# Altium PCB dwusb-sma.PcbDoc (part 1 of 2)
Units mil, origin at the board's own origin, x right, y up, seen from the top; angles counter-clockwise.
Board outline 1415 x 748.03 mil, 4 copper layers (Component Side, Ground Plane, Power Plane, Solder Side), stack 62.214 mil thick; 104 components, 67 nets, 356 pads, 248 vias.
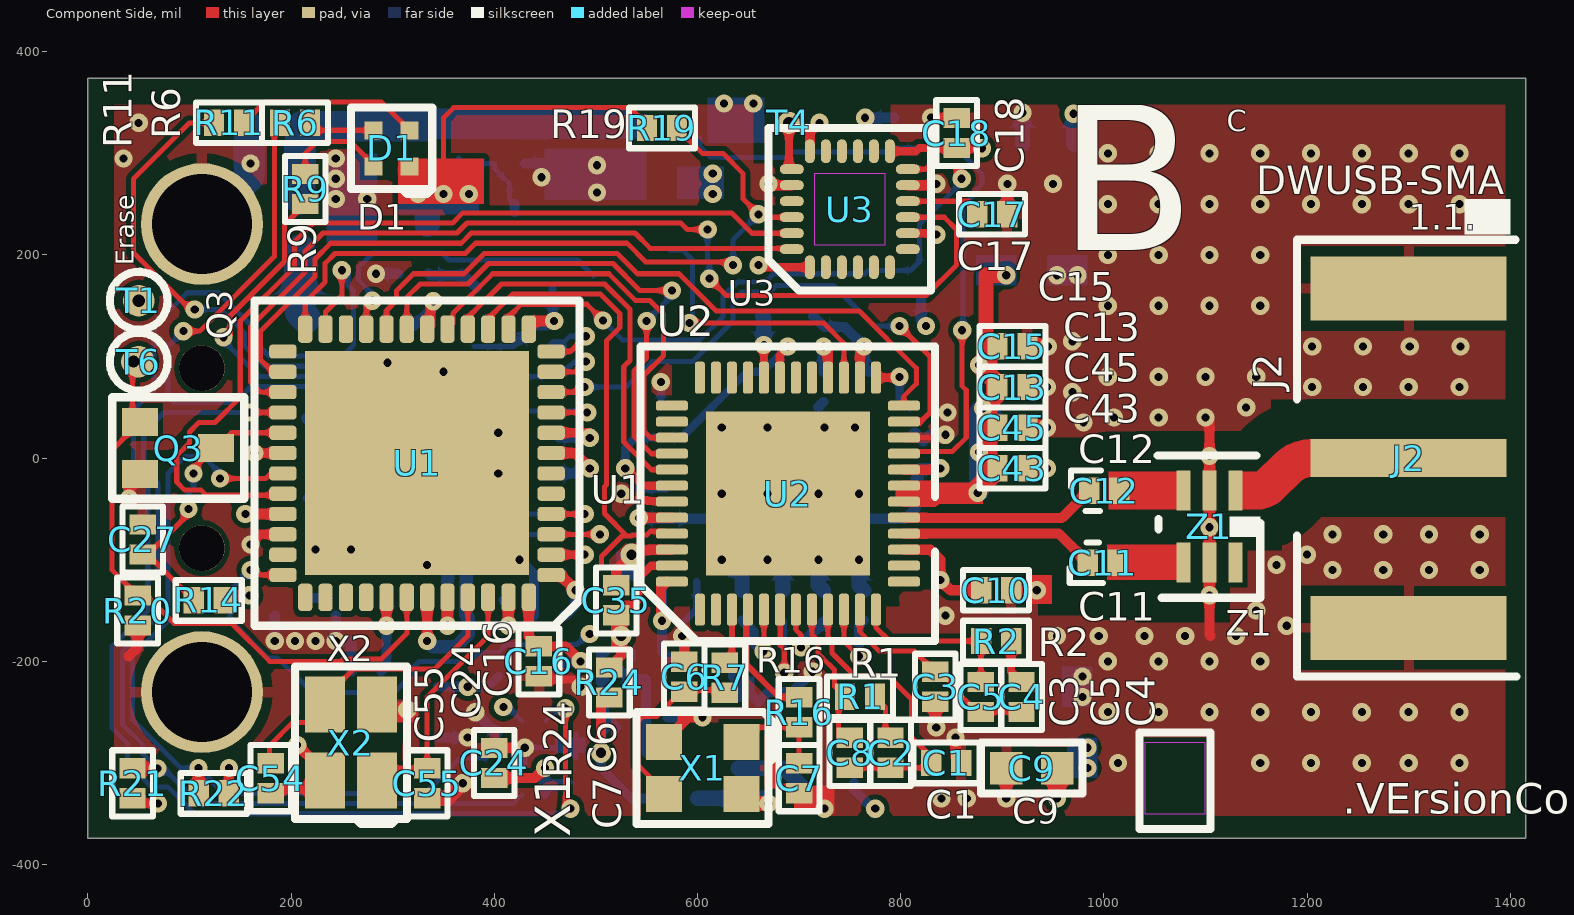
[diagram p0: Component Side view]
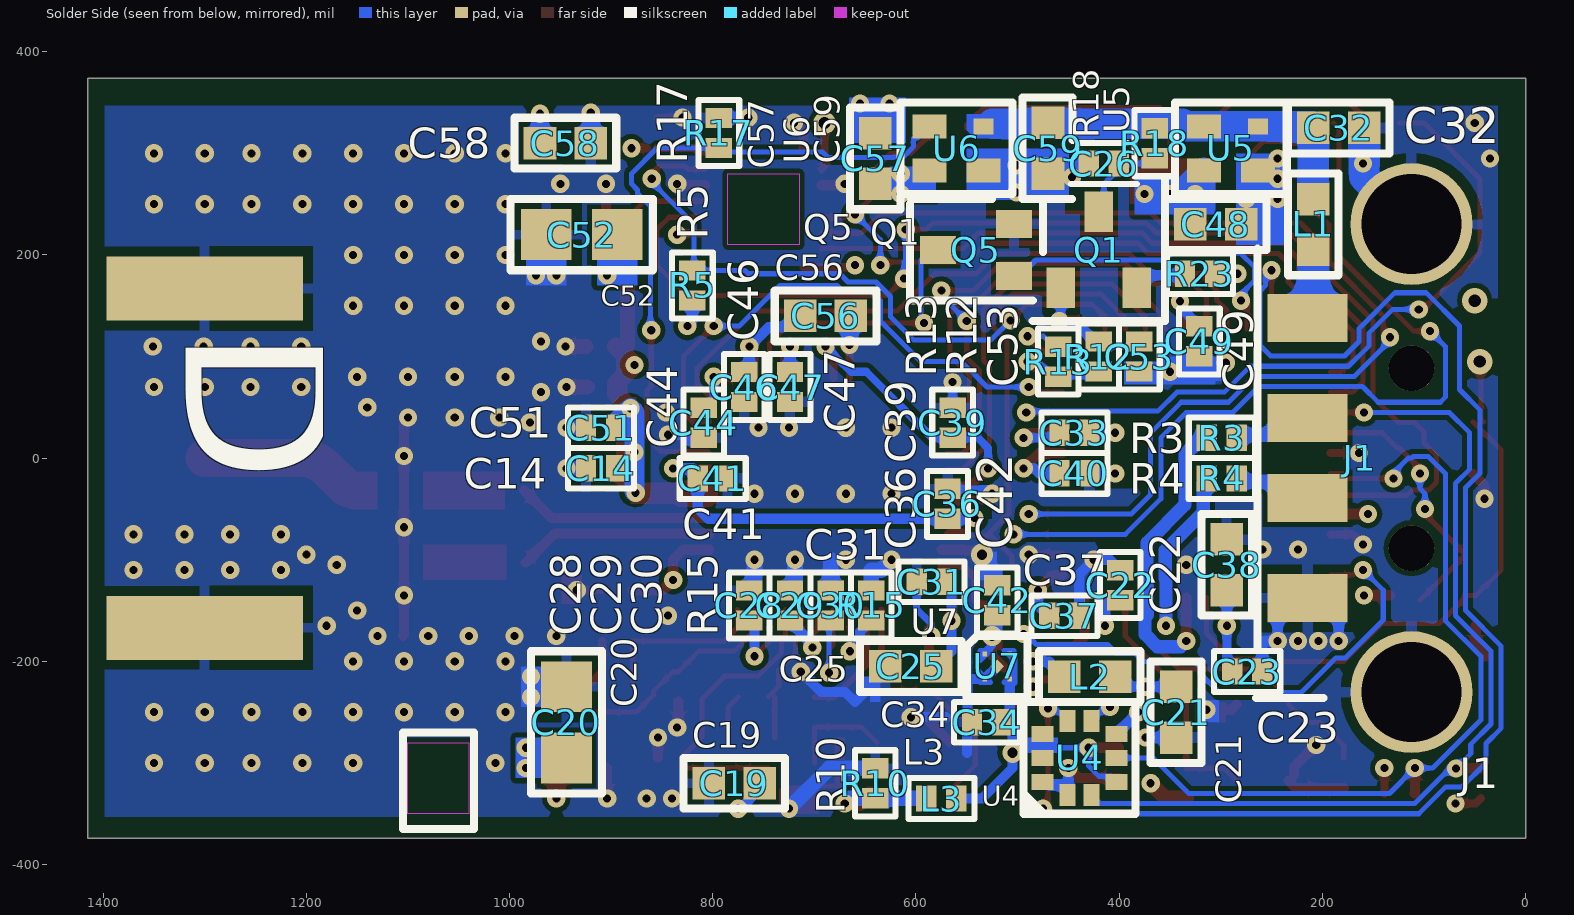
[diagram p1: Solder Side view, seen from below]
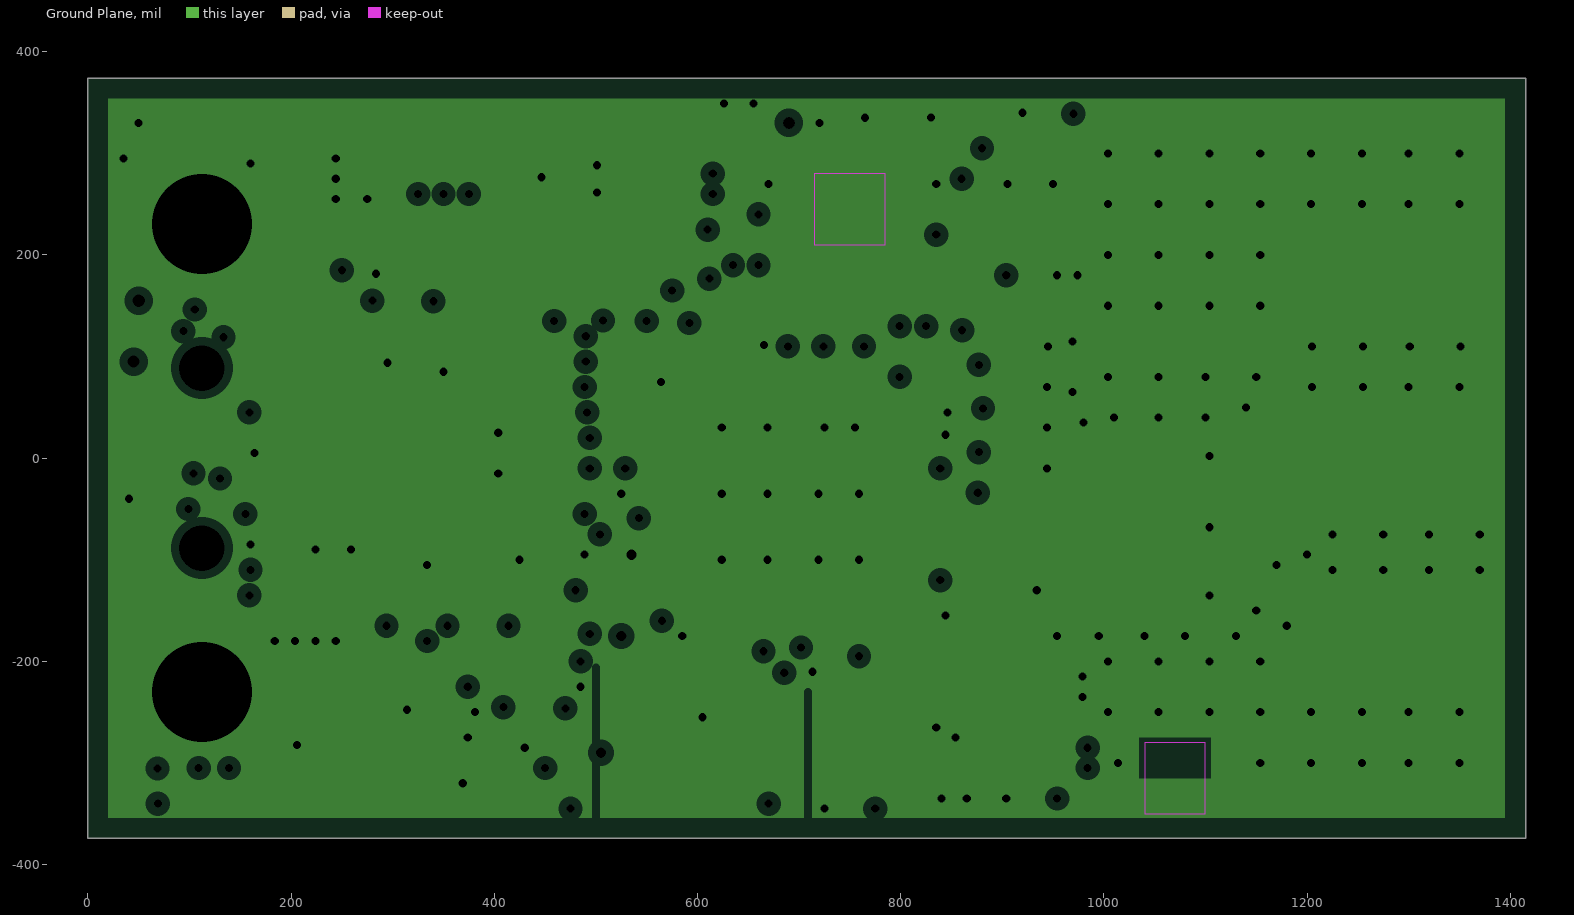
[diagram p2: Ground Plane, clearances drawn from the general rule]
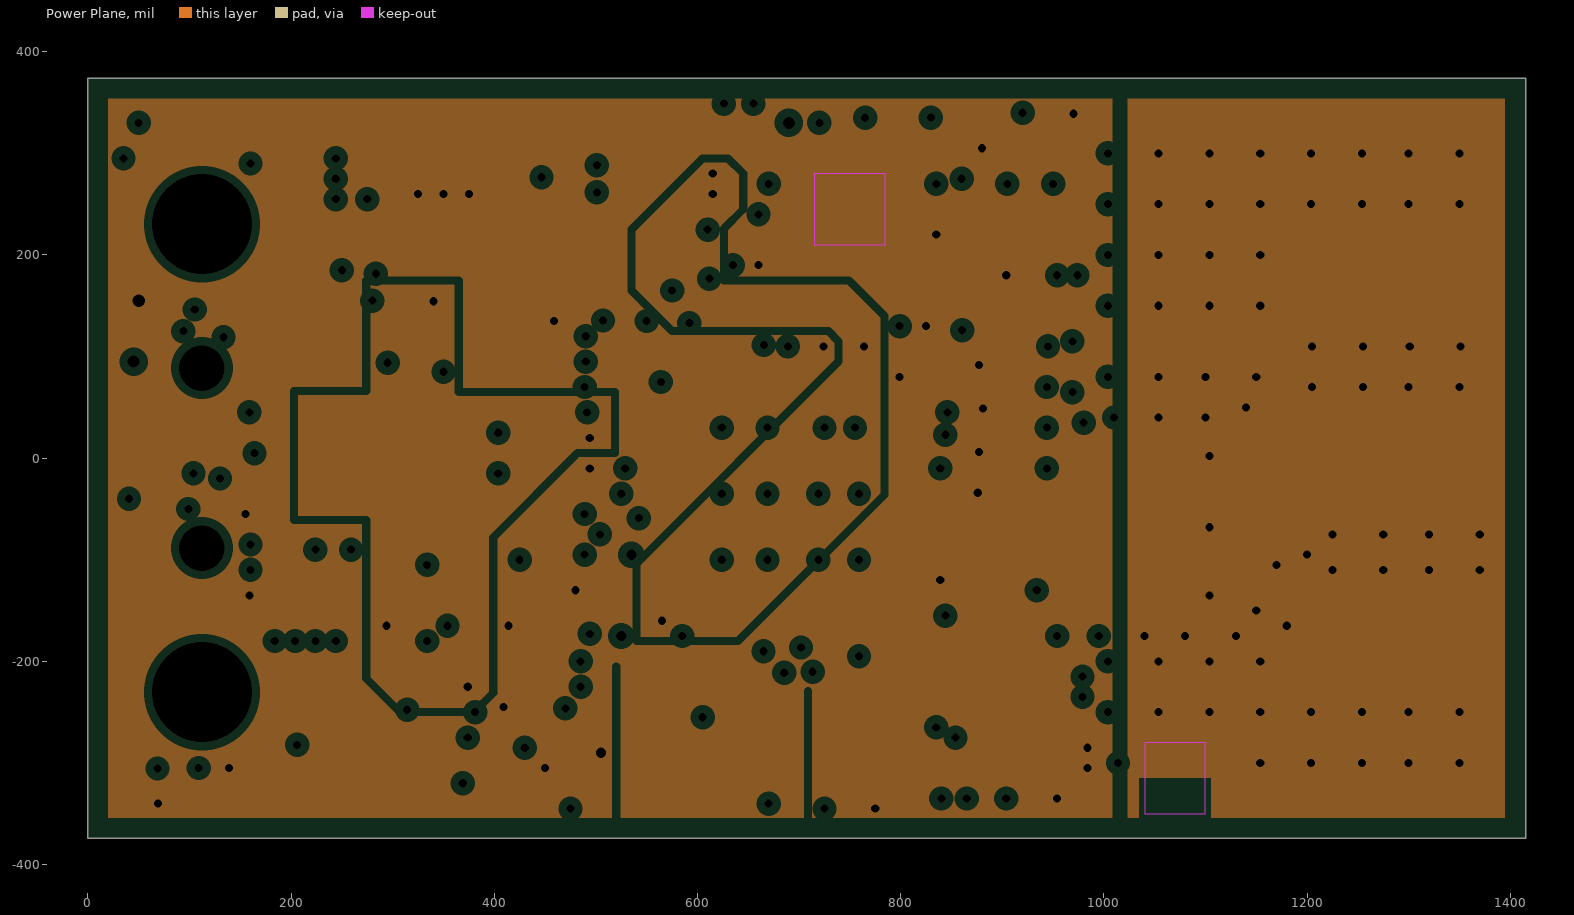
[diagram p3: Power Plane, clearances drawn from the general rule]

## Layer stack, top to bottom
Top Solder: solder mask 0.4, Solder Resist, Dk 3.5
Component Side: signal copper 1.4
Dielectric1: core 20.0787, FR-4, Dk 4.5
Ground Plane: plane copper 1.4, net GND
Dielectric2: prepreg 16.4567, FR-4, Dk 4.5
Power Plane: plane copper 1.4, net (Multiple Nets)
Dielectric3: core 20.0787, FR-4, Dk 4.5
Solder Side: signal copper 1.4
Bottom Solder: solder mask 0.4, Solder Resist, Dk 3.5

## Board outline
0,-374.02 1415,-374.02 1415,374.02 0,374.02

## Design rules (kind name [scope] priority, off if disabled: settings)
AcuteAngle [All] p1: minimum=7.50000000000000E+0001 checktracksonly=FALSE
AssemblyTestPointUsage [All] p1 off:
AssemblyTestpoint [All] p1 off: testpointundercomponent=TRUE minsize=30 maxsize=100 preferedsize=60 minholesize=0 maxholesize=40 preferedholesize=32 testpointgrid=1 usegrid=TRUE gridtolerance=0.01 allowsidetop=TRUE allowsidebottom=TRUE
Clearance Clearance_1 [(InNamedPolygon('top-ground')) vs InNet('ANTENNA')or InNet('BAL_P')or InNet('BAL_N')or InNet('RF_N')or InNet('RF_P')] p1: gap=39.37
Clearance [All] p2: gap=5
ComponentClearance ComponentClearance_2 [All] p1: gap=10 collisioncheckmode=3 verticalgap=10 showdistances=FALSE
ComponentClearance ComponentClearance_1 [InComponent('T2')] p2: gap=-500 collisioncheckmode=3 verticalgap=-500 showdistances=FALSE
ComponentClearance [InComponent('J1') vs InComponent('J2')] p3: gap=-1000 collisioncheckmode=3 verticalgap=-10000 showdistances=FALSE
DiffPairsRouting [All] p1: maxlimit=10 minlimit=5 mostfreqgap=5 toplayer_minwidth=9.06 toplayer_maxwidth=45 toplayer_prefwidth=9.25 bottomlayer_minwidth=9.06 bottomlayer_maxwidth=45 bottomlayer_prefwidth=9.25 maxuncoupledlength=500
FabricationTestPointUsage [All] p1 off: valid=0 allowmultiple=FALSE
FabricationTestpoint [All] p1 off: side=3 testpointundercomponent=TRUE minsize=30 maxsize=100 preferedsize=60 minholesize=0 maxholesize=40 preferedholesize=32 testpointgrid=1 allowsidetop=TRUE allowsidebottom=TRUE usegrid=TRUE gridtolerance=0.01
Height [All] p1: minheight=0 maxheight=2000 prefheight=500
HoleSize [All] p1: absolutevalues=TRUE maxlimit=300 minlimit=5 maxpercent=80.000 minpercent=20.000
MinimumAnnularRing [All] p1: minimumring=5
MinimumSolderMaskSliver [All] p1: minsoldermaskwidth=4
PlaneClearance [All] p1: clearance=8
PlaneConnect [All] p1: planeconnectstyle=Direct reliefexpansion=20 reliefentries=4 reliefconductorwidth=10 reliefairgap=10
PolygonConnect PolygonConnect_1 [(InPadClass('All Pads'))] p1: connectstyle=Relief reliefconductorwidth=10 reliefentries=4 polygonreliefangle="90 Angle" airgapwidth=10
PolygonConnect [All] p2: connectstyle=Direct reliefconductorwidth=10 reliefentries=4 polygonreliefangle="90 Angle" airgapwidth=10
RoutingVias [All] p1: holewidth=12 width=24 viastyle="Through Hole" minholewidth=6 minwidth=16 maxholewidth=40 maxwidth=50
SilkToSilkClearance [All] p1: silktosilkclearance=0
SilkToSolderMaskClearance SilkscreenOverComponentPads [IsPad] p1: minsilkscreentomaskgap=0 clearancetoexposedcopper=TRUE
SolderMaskExpansion [All] p1: expansion=0
Width "Schematic Width Constraint_4" [InNet('BAL_N')] p1: maxlimit=14.3 minlimit=13.43 preferedwidth=13.66 impedancedriven=TRUE minimp=80.000000 maximp=82.000000 favimp=81.450000
Width "Schematic Width Constraint_3" [InNet('RF_P')] p2: maxlimit=14.3 minlimit=13.43 preferedwidth=13.66 impedancedriven=TRUE minimp=80.000000 maximp=82.000000 favimp=81.450000
Width "Schematic Width Constraint_2" [InNet('RF_N')] p3: maxlimit=14.3 minlimit=13.43 preferedwidth=13.66 impedancedriven=TRUE minimp=80.000000 maximp=82.000000 favimp=81.450000
Width "Schematic Width Constraint_1" [InNet('BAL_P')] p4: maxlimit=14.3 minlimit=13.43 preferedwidth=13.66 impedancedriven=TRUE minimp=80.000000 maximp=82.000000 favimp=81.450000
Width [All] p5: maxlimit=200 minlimit=5 preferedwidth=5
17 further rules are at their usual default settings.

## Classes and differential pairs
component class sam4s-mpu9250: C9 C16 C17 C18 C19 C21 C22 C23 C24 C26 C27 C32 C33 C37 C38 C40 C48 C49 C53 C54 C55 C58 D1 J1 L1 L2 Q1 Q3 R3 R4 R5 R6 R9 R11 R12 R13 R14 R18 R19 R20 R21 R22 R23 T1 T4 T6 U1 U3 U4 U5 X2
component class dw1000: C1 C2 C3 C4 C5 C6 C7 C8 C10 C11 C12 C13 C14 C15 C20 C25 C28 C29 C30 C31 C34 C35 C36 C39 C41 C42 C43 C44 C45 C46 C47 C51 C52 C56 C57 C59 J2 L3 Q5 R1 R2 R7 R10 R15 R16 R17 R24 U2 U6 U7 X1 Z1
component class dwusb-sma: A1
differential pair RF: +RF_P -RF_N
differential pair USB-DATA: +USB-DATA_P -USB-DATA_N
differential pair BAL: +BAL_P -BAL_N
differential pair USB: +USB_P -USB_N

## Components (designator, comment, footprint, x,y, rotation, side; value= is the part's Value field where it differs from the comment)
A1 "A_DG-OUTLINE-DG-270X100" DG-270X100 1435,-550 r180 top
C1 "C_CAP_0402" 0402 845,-300 r180 top
C2 "C_CAP_0402" 0402 790,-290 r90 top
C3 "C_CAP_0402" 0402 833.94,-225 r270 top
C4 "C_CAP_0402" 0402 918.94,-235 r90 top
C5 "C_CAP_0402" 0402 878.94,-235 r90 top
C6 "C_CAP_0402" 0402 587,-215 r270 top
C7 "C_CAP_0402" 0402 700,-315 r90 top
C8 "C_CAP_0402" 0402 750,-290 r270 top
C9 "C_CAP_0603" 0603 928.94,-305 r180 top
C10 "C_CAP_0402" 0402 893.94,-130 r0 top
C11 "C_CAP_0402" 0402 998.94,-102.87 r0 top
C12 "C_CAP_0402" 0402 1000.24,-32.01 r0 top
C13 "C_CAP_0402" 0402 910,70 r0 top
C14 "C_CAP_0402" 0402 910,-10 r0 bottom
C15 "C_CAP_0402" 0402 910,110 r0 top
C16 "C_CAP_0402" 0402 443.94,-200 r270 top
C17 "C_CAP_0402" 0402 890,240 r0 top
C18 "C_CAP_0402" 0402 855,320 r90 top
C19 "C_CAP_0603" 0603 778.94,-320 r0 bottom
C20 "C_CAP_0805" 0805 943.94,-260 r90 bottom
C21 "C_CAP_0603" 0603 343.94,-250 r270 bottom
C22 "C_CAP_0402" 0402 398.94,-125 r90 bottom
C23 "C_CAP_0402" 0402 273.94,-210 r180 bottom
C24 "C_CAP_0402" 0402 400,-300 r90 top
C25 "C_CAP_0603" 0603 605,-205 r0 bottom
C26 "C_CAP_0402" 0402 415,290 r0 bottom
C27 "C_CAP_0402" 0402 53.94,-80 r90 top
C28 "C_CAP_0402" 0402 763.94,-145 r90 bottom
C29 "C_CAP_0402" 0402 723.94,-145 r90 bottom
C30 "C_CAP_0402" 0402 683.94,-145 r90 bottom
C31 "C_CAP_0402" 0402 584.53,-121.61 r0 bottom
C32 "C_CAP_0603" 0603 183.94,325 r180 bottom
C33 "C_CAP_0402" 0402 443.94,25 r180 bottom
C34 "C_CAP_0402" 0402 530,-260 r0 bottom
C35 "C_CAP_0402" 0402 520,-140 r90 top
C36 "C_CAP_0402" 0402 568.94,-45 r90 bottom
C37 "C_CAP_0402" 0402 453.94,-155 r180 bottom
C38 "C_CAP_0603" 0603 293.94,-105 r90 bottom
C39 "C_CAP_0402" 0402 563.94,35 r90 bottom
C40 "C_CAP_0402" 0402 443.94,-15 r180 bottom
C41 "C_CAP_0402" 0402 800,-20 r180 bottom
C42 "C_CAP_0402" 0402 520,-140 r90 bottom
C43 "C_CAP_0402" 0402 910,-10 r0 top
C44 "C_CAP_0402" 0402 808.94,35 r270 bottom
C45 "C_CAP_0402" 0402 910,30 r0 top
C46 "C_CAP_0402" 0402 768.94,70 r270 bottom
C47 "C_CAP_0402" 0402 723.94,70 r270 bottom
C48 "C_CAP_0603" 0603 305,230 r180 bottom
C49 "C_CAP_0402" 0402 321,115 r270 bottom
C51 "C_CAP_0402" 0402 910,30 r0 bottom
C52 "C_CAP_0805" 0805 928.94,220 r0 bottom
C53 "C_CAP_0402" 0402 380,100 r270 bottom
C54 "C_CAP_0402" 0402 180,-315 r270 top
C55 "C_CAP_0402" 0402 333.94,-320 r270 top
C56 "C_CAP_0603" 0603 688.94,140 r180 bottom
C57 "C_CAP_0603" 0603 640,295 r90 bottom
C58 "C_CAP_0603" 0603 945,310 r180 bottom
C59 "C_CAP_0603" 0603 470,305 r270 bottom
D1 "LED RGB SQUARE CLEAR SMD" 0404-3C-LED 298.94,305 r180 top
J1 "J_USBA-PLUG_48037-2200" 48037-2200 3.94,0 r90 bottom locked
J2 "J01340" 142-0701-801 1415,0 r270 top locked
L1 "L_IND_0603" 0603 208.94,230 r90 bottom
L2 "L_IND_0603" 0603 428.94,-215 r0 bottom
L3 "L_IND_0402" 0402 575,-335 r0 bottom
Q1 "Q_JFET-P_SOT23" SOT23 420,205 r90 bottom
Q3 "Q00171" SC70 88.94,10 r0 top
Q5 "Q00171" SC70 541,205 r0 bottom
R1 "R_RES_0402" 0402 760,-235 r0 top
R2 "R_RES_0402" 0402 893.94,-180 r180 top
R3 "R_RES_0402" 0402 298.94,20 r180 bottom
R4 "R_RES_0402" 0402 298.94,-20 r180 bottom
R5 "R_RES_0402" 0402 820,170 r270 bottom
R6 "R_RES_0402" 0402 203.94,330 r0 top
R7 "R_RES_0402" 0402 627,-216 r270 top
R9 "R_RES_0402" 0402 213.94,265 r90 top
R10 "R_RES_0402" 0402 640,-320 r270 bottom
R11 "R_RES_0402" 0402 138.94,330 r0 top
R12 "R_RES_0402" 0402 420,100 r90 bottom
R13 "R_RES_0402" 0402 460,95 r270 bottom
R14 "R_RES_0402" 0402 118.94,-140 r0 top
R15 "R_RES_0402" 0402 643.94,-145 r270 bottom
R16 "R_RES_0402" 0402 700,-250 r270 top
R17 "R_RES_0402" 0402 793.94,320 r270 bottom
R18 "R_RES_0402" 0402 365,310 r270 bottom
R19 "R_RES_0402" 0402 565,325 r180 top
R20 "R_RES_0402" 0402 48.94,-150 r90 top
R21 "R_RES_0402" 0402 43.94,-320 r270 top
R22 "R_RES_0402" 0402 123.94,-330 r0 top
R23 "R_RES_0402" 0402 320.44,181.5 r0 bottom
R24 "R_RES_0402" 0402 513.31,-220.75 r90 top
T1 "T_TESTPOINT-PAD_T31ES" T31ES 50,155 r270 top
T4 "T_TESTPOINT_H22D12EDS" H22D12EDS 690,330 r0 top locked
T6 "T_TESTPOINT-PAD_T31ES" T31ES 50,95 r270 top
U1 "U00965" QFN48 323.94,-5 r180 top
U2 "U00956" QFN48-6M0 688.94,-35 r90 top
U3 "U00945" MPU-9250 750,245 r90 top
U4 "U01153" LGA10-2M5 438.94,-295 r90 bottom
U5 "U_LXDC2HL_LXDC2HL" LXDC2HL 290,305 r0 bottom
U6 "U00987" LXDC2HL 560,305 r0 bottom
U7 "U_TCR2LN_SDFN4" SDFN4 520,-205 r180 bottom
X1 "X_XTAL4P2G_ECX-2236" 7Z-2M0X1M6-4P 605,-305 r180 top
X2 "X_XTAL4P2G_ECX-2236" ECX-2236 258.94,-280 r90 top
Z1 "Z_WE-BAL_0805-6" 0805-6 1103.94,-67.44 r270 top

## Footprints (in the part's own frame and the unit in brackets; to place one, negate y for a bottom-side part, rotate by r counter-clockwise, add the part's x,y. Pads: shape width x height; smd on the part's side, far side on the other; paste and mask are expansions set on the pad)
7Z-2M0X1M6-4P [mm]
  rect 0.9x0.9 smd: 1(-0.97,-0.65) 2(0.97,-0.65) 3(0.97,0.65) 4(-0.97,0.65)
  silkscreen extent -1.78,-1.4 1.65,1.4, body extent -1.28,-1.05 1.25,1.05, height 0.75
142-0701-801 [mil]
  rect 37.4x193 smd paste-1000: 1(0,-115)
  rect 63x193 smd paste-1000: 2(-167,-115) 3(167,-115)
  rect 63x193 smd far side paste-1000: 4(167,-115) 5(-167,-115)
  silkscreen extent -215,-225 215,-9, body extent -187,-187 188,375, height 171
0402 [mil]
  rect 20x26 smd: 1(-14.76,0) 2(14.76,0)
  silkscreen extent -32,-20 32,20, body extent -20,-10 20,10, height 14
0404-3C-LED [mm]
  rect 0.45x0.45 smd: 1(-0.45,0.45) 2(0.45,0.45) 3(0.45,-0.45) 4(-0.45,-0.45)
  silkscreen extent -1.02,-1.02 1.02,1.14, body extent -0.5,-0.5 0.5,0.5, height 0.25
0603 [mil]
  rect 32x32 smd: 1(-25,0) 2(25,0)
  silkscreen extent -50,-25 50,25, body extent -30,-15 30,15, height 30
0805 [mil]
  rect 50x50 smd: 1(-35,0) 2(35,0)
  silkscreen extent -70,-35 70,35, body extent -40,-25 40,25, height 50
0805-6 [mm]
  rect 1x0.35 smd: 1(-0.9,0.65) 2(-0.9,0) 3(-0.9,-0.65) 4(0.9,-0.65) 5(0.9,0) 6(0.9,0.65)
  silkscreen extent -1.78,-1.29 1.78,1.27, body extent -0.67,-1.05 0.67,1.05, height 0.95
48037-2200 [mm]
  rect 1.2x2 smd: 1(3.5,5.35) 2(1,5.35) 3(-1,5.35) 4(-3.5,5.35)
  round 3.048 hole 2.5: 5(5.85,2.75) 6(-5.85,2.75)
  round 1.143 hole 1.143 unplated: ""(-2.25,2.75) ""(2.25,2.75)
  silkscreen extent -6,4.95 5.24,6.63, body extent -6.02,-15.01 6.03,5.94, height 2.1
DG-270X100 [mil]
  Keep-Out Layer region: 394.99,-269.99 394.99,-199.99 334.99,-199.99 334.99,-269.99
ECX-2236 [mm]
  rect 1.4x1 smd: 1(-0.95,-0.65) 2(0.95,-0.65) 3(0.95,0.65) 4(-0.95,0.65)
  silkscreen extent -2.03,-1.4 1.91,1.4, body extent -1.3,-1.05 1.3,1.05, height 0.65
H22D12EDS [mil]
  round 22 hole 12: 1(0,0)
  body extent -11,-11 11,11, height 1
LGA10-2M5 [mm]
  rect 0.55x0.4 smd: 1(-0.925,0.3) 2(-0.925,-0.3) 6(0.925,-0.3) 7(0.925,0.3)
  rect 0.4x0.55 smd: 3(-0.6,-0.925) 4(0,-0.925) 5(0.6,-0.925) 8(0.6,0.925) 9(0,0.925) 10(-0.6,0.925)
  silkscreen extent -1.4,-1.4 1.4,1.4, body extent -1.25,-1.25 1.25,1.25, height 1.1
LXDC2HL [mm]
  rect 0.5x0.4 smd: 1(-0.675,-0.55)
  rect 0.85x0.6 smd: 2(0.675,-0.55) 3(0.675,0.55) 4(-0.675,0.55)
  Component Side region: -1.1,-0.85 -0.25,-0.85 -0.25,-0.45 -0.45,-0.25 -1.1,-0.25
  silkscreen extent -1.4,-1.14 1.4,1.14, body extent -1.25,-1 1.25,1, height 0.6
MPU-9250 [mm]
  rrect100% 0.6x0.25 smd: 1(-1.45,1) 2(-1.45,0.6) 3(-1.45,0.2) 4(-1.45,-0.2) 5(-1.45,-0.6) 6(-1.45,-1) 13(1.45,-1) 14(1.45,-0.6) 15(1.45,-0.2) 16(1.45,0.2) 17(1.45,0.6) 18(1.45,1)
  rrect100% 0.25x0.6 smd: 7(-1,-1.45) 8(-0.6,-1.45) 9(-0.2,-1.45) 10(0.2,-1.45) 11(0.6,-1.45) 12(1,-1.45) 19(1,1.45) 20(0.6,1.45) 21(0.2,1.45) 22(-0.2,1.45) 23(-0.6,1.45) 24(-1,1.45)
  Keep-Out Layer region: -0.889,-0.889 0.889,-0.889 0.889,0.889 -0.889,0.889
  silkscreen extent -2.03,-2.03 2.03,2.03, body extent -1.5,-1.5 1.5,1.5, height 1.1
QFN48 [mil]
  rrect50% 27x14 smd: 1(-132,110) 2(-132,90) 3(-132,70) 4(-132,50) 5(-132,30) 6(-132,10) 7(-132,-10) 8(-132,-30) 9(-132,-50) 10(-132,-70) 11(-132,-90) 12(-132,-110) 25(132,-110) 26(132,-90) 27(132,-70) 28(132,-50) 29(132,-30) 30(132,-10) 31(132,10) 32(132,30) 33(132,50) 34(132,70) 35(132,90) 36(132,110)
  rrect50% 14x27 smd: 13(-110,-132) 14(-90,-132) 15(-70,-132) 16(-50,-132) 17(-30,-132) 18(-10,-132) 19(10,-132) 20(30,-132) 21(50,-132) 22(70,-132) 23(90,-132) 24(110,-132) 37(110,132) 38(90,132) 39(70,132) 40(50,132) 41(30,132) 42(10,132) 43(-10,132) 44(-30,132) 45(-50,132) 46(-70,132) 47(-90,132) 48(-110,132)
  rect 220.47x220.47 smd paste-1000: 49(0,0)
  silkscreen extent -160,-160 160,160, body extent -138,-138 138,138, height 35
QFN48-6M0 [mm]
  rrect50% 0.8x0.25 smd: 1(-2.9,2.2) 2(-2.9,1.8) 3(-2.9,1.4) 4(-2.9,1) 5(-2.9,0.6) 6(-2.9,0.2) 7(-2.9,-0.2) 8(-2.9,-0.6) 9(-2.9,-1) 10(-2.9,-1.4) 11(-2.9,-1.8) 12(-2.9,-2.2) 25(2.9,-2.2) 26(2.9,-1.8) 27(2.9,-1.4) 28(2.9,-1) 29(2.9,-0.6) 30(2.9,-0.2) 31(2.9,0.2) 32(2.9,0.6) 33(2.9,1) 34(2.9,1.4) 35(2.9,1.8) 36(2.9,2.2)
  rrect50% 0.25x0.8 smd: 13(-2.2,-2.9) 14(-1.8,-2.9) 15(-1.4,-2.9) 16(-1,-2.9) 17(-0.6,-2.9) 18(-0.2,-2.9) 19(0.2,-2.9) 20(0.6,-2.9) 21(1,-2.9) 22(1.4,-2.9) 23(1.8,-2.9) 24(2.2,-2.9) 37(2.2,2.9) 38(1.8,2.9) 39(1.4,2.9) 40(1,2.9) 41(0.6,2.9) 42(0.2,2.9) 43(-0.2,2.9) 44(-0.6,2.9) 45(-1,2.9) 46(-1.4,2.9) 47(-1.8,2.9) 48(-2.2,2.9)
  rect 4.1x4.1 smd paste-25.4: 49(0,0)
  silkscreen extent -3.68,-3.68 3.68,3.68, body extent -3,-3 3,3, height 1.19
SC70 [mm]
  rect 0.9x0.7 smd: 1(-0.95,0.65) 2(-0.95,-0.65) 3(0.95,0)
  silkscreen extent -1.65,-1.27 1.65,1.27, body extent -1.2,-1 1.2,1, height 1
SDFN4 [mm]
  rect 0.12x0.12 smd paste+0 mask-0.051: 1(-0.312,0.312) 2(-0.312,-0.312) 3(0.312,-0.312) 4(0.312,0.312)
  rect 0.25x0.25 smd rot 135 paste+0 mask+0.051: 5(0,0)
  Component Side region: -0.425,0.145 -0.425,0.4 -0.17,0.4
  Component Side region: -0.425,-0.4 -0.425,-0.145 -0.17,-0.4
  Component Side region: 0.425,-0.4 0.425,-0.145 0.17,-0.4
  Component Side region: 0.425,0.145 0.425,0.4 0.17,0.4
  Component Side lines w0.127: 0.425,-0.4 0.17,-0.4 0.425,-0.145 0.425,-0.4 ; 0.425,0.145 0.17,0.4 0.425,0.4 0.425,0.145 ; -0.17,-0.4 -0.425,-0.4 -0.425,-0.145 -0.17,-0.4 ; -0.17,0.4 -0.425,0.4 -0.425,0.145 -0.17,0.4
  silkscreen extent -0.76,-0.76 0.76,0.76, body extent -0.4,-0.4 0.4,0.4, height 0.4
SOT23 [mil]
  rect 40x28 smd: 1(-37.4,37.4) 2(-37.4,-37.4) 3(37.4,0)
  silkscreen extent -70,-65 70,65, body extent -55,-57 55,57, height 39
T31ES [mil]
  round 31 smd paste-100: 1(0,0)
  silkscreen extent -28,-28 28,28

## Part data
A1: library part A02065, "Ciholas Blank DWUSB SMA PCB Revision 1.1.0"
C1 C3 C15 C16 C17 C18 C22 C23 C24 C27 C28 C29 C30 C31 C33 C34 C35 C36 C37 C39 C40 C41 C44 C46 C47 C49 C51 C53: library part C00136, "Capacitor 100nF 10V Ceramic X5R 0402"
C2: library part C00457, "Ceramic Capacitor 0402 27pF NP0"
C4: library part C00460, "CAP CER 820pF 50V 2% NP0 0402"
C5: library part C00459, "CAP CER 18PF 50V 2% NP0 0402"
C6 C7 C11 C12: library part C00461, "CAP CER 12pF 50V 2% NP0 0402"
C8 C54 C55: library part C00458, "Ceramic Capacitor 0402 1.2pF NP0"
C9 C19 C21 C25 C56 C58: library part C00213
C10: library part C00137, "Capacitor 10nF 25V Ceramic X7R 0402"
C13 C14: library part C00441, "CAP CER 10PF 50V 5% NP0 0402"
C20 C52: library part C00468, "CAP CER 47UF 6.3V 20% X5R 0805"
C26: library part C00434, "CAP CER 100PF 50V 5% NP0 0402"
C32 C59: library part C00431, "CAP CER 10UF 16V 20% X5R 0603"
C38: library part C00213, "Capacitor 4.7uF 10V Ceramic Y5V 0603"
C42: library part C00342, "Capacitor 4.7uF 6.3V Ceramic X5R 20% 0402"
C43 C45: library part C00462, "Ceramic Capacitor 0402 330pF NP0"
C48 C57: library part C00171, "Capacitor 10uF 6.3V Ceramic X5R 0603"
D1: library part D00360
J1: library part J01292, "USB Connectors A Type SMT"
J2: "RF SMA End Launch Jack 0.062\" Thick 0.31\" Shaft"
L1 L2: library part L00246, "Ferrite Bead 1.5k@100Mhz SMD 0603 500mA"
L3: library part L00272, "FERRITE BEAD 600 OHM 0402"
Q3 Q5: "MOSFET N-CH 50V 360mA SC70-3"
R1: library part R00702, "RES 16K OHM 1/16W 1% 0402 SMD"
R2: library part R00703, "RES 270 OHM 1/10W 1% 0402 SMD"
R3 R4: library part R00714, "RES 27 OHM 1/10W 1% 0402 SMD"
R5 R12 R13 R17 R19 R20: library part R00696, "RES 100K OHM 1/16W 1% 0402 SMD"
R6: library part R00726, "RES 475 OHM 1/10W 1% 0402 SMD"
R7 R10 R16 R18 R24: library part R00661, "Resistor 0 ohm 1/16W 5% 0402 SMD"
R9: library part R00698, "RES 2.00K OHM 1/10W 1% 0402 SMD"
R11: library part R00547, "RES 634 OHM 1/16W 1% 0402 SMD"
R14 R15 R21 R22: library part R00704, "RES 11K OHM 1/10W 1% 0402 SMD"
R23: library part R00784, "RES 4.53K OHM 1/10W 1% 0402 SMD"
T1 T6: library part T00003
T4: library part T00015, "Test Point 0.012\" diameter hole with 0.022\" diameter pad"
U1: "Atmel ATSAM4S Series MCU 48-Pin QFN"
U2: "Ultra Wideband low-power transceiver QFN48-6M0"
U3: "9-AXIS MEMS ACCELEROMTER/GYROSCOPE/MAG"
U4: "IC PRESSURE SENSOR 260-1260 hPa SMD LGA10-2M5"
U5: library part U01049, "DC/DC Converter 3.3V 300MA SMD"
U6: "DC/DC Converter 1.8V 600MA SMD"
X2: library part X00141, "Crystal 12MHz 12pF SMD"
Z1: library part Z00014, "RF Balun 3.0-8.0GHz UWB SMD"

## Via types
v1: diameter 18, hole 8, Component Side to Solder Side, tented both sides, 165 vias
v2: diameter 18, hole 8, Component Side to Solder Side, 78 vias
v3: diameter 20, hole 10, Component Side to Solder Side, tented both sides, 2 vias
v4: diameter 25, hole 12, Component Side to Solder Side, 2 vias
v5: diameter 22, hole 10, Component Side to Solder Side, tented both sides, 1 vias

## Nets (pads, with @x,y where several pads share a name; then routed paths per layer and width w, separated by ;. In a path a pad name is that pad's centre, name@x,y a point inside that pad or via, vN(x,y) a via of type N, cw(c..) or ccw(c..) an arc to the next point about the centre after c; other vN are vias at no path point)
1V2: C21.1 C23.1 C33.1 C38.1 C49.1 L2.1 U1.8 U1.18 U1.41 | length 307.2
  Component Side w9: v1(293.94,-165) U1.41@293.94,-137 ; U1.18@333.94,127 337.44,130.5 337.44,151.94 v1(340,154.5) ; U1.8@455.94,25 493.94,25 v2(493.94,20)
  Solder Side w9: C23.1@288.7,-210 293.94,-204.76 v1(293.94,-165) C38.1@293.94,-140 ; C49.1@321,129.76 340,148.76 v1(340,154.5) ; C21.1@343.94,-225 v2(373.94,-225) 393.94,-225 L2.1@403.94,-215 ; C33.1@458.7,25 463.7,20 v2(493.94,20)
1V8: C25.1 C31.1 C46.1 C56.1 C57.1 U2.26 U2.48 U6.3 | length 251.9
  Component Side w10: v1(565,-160) 563.94,-158.94 563.94,-127.44 U2.48@569.76,-121.61 ; U2.26@759.8,79.17 759.8,105.87 v2(763.94,110)
  Solder Side w10: C31.1@565,-126.38 v1(565,-160) 565,-190 C25.1@580,-205 ; C25.1@582.5,-202.5 C25.1@585,-205 ; C56.1@713.94,140 724.94,129 744.94,129 v2(763.94,110) 763.94,89.76 C46.1@768.94,84.76
  other v1: 615,260 615,280
3V3: C9.1 C10.1 C13.1 C14.1 C15.1 C18.1 C19.1 C20.1 C22.1 C24.1 C34.1 C37.1 C40.1 C43.1 C44.1 C45.1 C47.1 C48.1 C51.1 C52.1 C53.1 C58.1 D1.1 L3.1 Q1.1 R5.2 R12.2 R14.2 R19.2 R21.2 R22.2 R24.1 T1.1 U1.1 U1.7 U1.13 U1.33 U1.47 U2.15 U2.18 U2.19 U2.25 U2.28 U3.1 U3.8 U3.13 U4.1 U4.6 U4.10 U5.3 U7.3 U7.4 | length 2194.3
  Component Side w5: D1.1@316.65,287.28 350,287.28 350,335 360,345 533.24,345 550.24,328 R19.2@550.24,325
  Component Side w8: R21.2@43.94,-334.76 49.17,-340 v1(68.94,-340) ; R22.2@138.7,-330 138.7,-305.24 v1(138.94,-305) ; v2@660,189.17 v2(660,190) ; v2@667.09,187.91 U3.1@710.63,187.91 ; U2.25@775.55,79.17 v1@798.94,79.17 ; U3.13@789.37,302.09 815.08,302.09 818.23,305.24 C18.1@855,305.24 ; U3.8@807.09,221.38 833.62,221.38 v2(835,220) ; C18.1@864.53,305 v1(880,305)
  Component Side w10: R14.2@133.7,-135 v2(158.94,-135) ; v1@158.94,-55 U1.33@191.94,-55 ; C24.1@400,-314.76 440.24,-314.76 v1(450,-305) ; v1(413.94,-165) U1.47@413.94,-137 ; U1.13@433.94,127 433.94,133.94 435,135 v1(458.94,135) ; U1.1@455.94,-115 465,-115 v1(480,-130) ; U1.7@455.94,5 478.94,5 v2(493.94,-10) ; v3(505,-290) 505,-243.82 R24.1@513.31,-235.51 ; v2(723.94,110) 728.31,105.63 U2.28@728.31,79.17 ; U2.15@803.11,-90.12 829.06,-90.12 838.94,-100 v2(838.94,-120) 848.94,-130 C10.1@879.17,-130 ; U2.18@803.11,-42.87 832.93,-42.87 ; U2.19@803.11,-27.13 829.19,-27.13 831.07,-29 ; 831.07,-29 832.93,-30.87 832.93,-42.87 ; 831.07,-29 846.81,-29 832.93,-42.87
  Component Side w15: v1@872,-34 873.94,-32.06 v1(875.87,-34) ; C15.1@895.24,110 883.94,110 883.94,180 v1(903.94,180) ; v2(953.94,-335) C9.1@953.94,-305
  Component Side w18: v1(881,49) 895.24,63.24 895.24,73.53 v1(877,91.76) C15.1@895.24,110
  Component Side w20: 846.81,-34 872,-34 C43.1@895.24,-10.76
  Solder Side w5: C53.1@380,109.76 418.94,109.76 R12.2@425.61,116.44 ; v1(408.94,-245) 413.54,-245 U4.6@427.13,-258.58 ; U4.1@450,-330.67 U4.1@450.75,-331.42 457.17,-325 468.98,-325 U4.10@475.35,-318.62 ; 503.27,-199.29 503.27,-190.07 504.08,-189.25 513.31,-189.25 ; v2@820,135 v2(825,130)
  Solder Side w8: Q1.1@457.4,167.6 457.4,136.54 v1(458.94,135) ; 504.04,-220.75 504.04,-192.7 U7.4@507.7,-192.7 ; U7.3@507.7,-217.3 U7.3@509.71,-219.32 ; v1(798.94,80) 798.94,59.76 C44.1@808.94,49.76
  Solder Side w10: C22.1@408.94,-139.76 413.94,-144.76 v1(413.94,-165) ; R12.2@425.61,116.44 439.79,130.61 451.48,130.61 v1@457.4,136.54 ; U4.1@450,-330.67 v1(450,-305) ; C40.1@458.7,-15 478.94,-15 483.94,-10 v2(493.94,-10) ; C37.1@468.7,-155 470,-155 480,-145 v1(480,-130) ; C34.1@507.7,-265 507.7,-220.75 ; C34.1@520.24,-265 C34.1@515.24,-260 505,-270.24 505,-280.24 v3(505,-290) 505,-305 535,-335 L3.1@560.24,-335 ; C47.1@723.94,84.76 v2(723.94,110) ; C19.1@753.94,-320 753.94,-326.14 772.8,-345 v1(775,-345) ; v2@820,135 R5.2@820,155.24
  Solder Side w15: C58.1@970,308.94 v1(970,338.94)
  Solder Side w20: v1@877,-32.87 v1(877,5.94) 877,45 v1(881,49) 895.24,34.76 C51.1@895.24,30
  Solder Side w25: U5.3@316.57,283.35 333.94,265.98 C48.1@333.94,230
  other v1: 983.94,-305 983.94,-285 155,-55 325,260 350,260 375,260
  other v4: 50,155
5V0: C32.1 C59.1 L1.2 R18.1 U5.1 U5.2 U6.1 | length 387.7
  Solder Side w30: L1.2@208.94,255 C32.1@208.94,325 210.59,326.65 282.36,326.65 335.51,326.65 337.86,329 U6.1@525,329
ANTENNA: J2.1 Z1.1 | length 161
  Component Side w37.4: 1150,-32.01 ccw(c1150,-12.71) 1163.64,-26.36 1180,-10 cw(c1204.14,-34.14) 1204.14,0 J2.1@1300,0
BAL_N: C12.2 Z1.3
BAL_P: C11.2 Z1.4
BLUE-LED: R6.1 U1.3 | length 902
  Component Side w5: v2(93.94,125) 110,125 183.5,198.5 183.5,324.33 R6.1@189.17,330 ; U1.3@455.94,-75 v2(503.94,-75)
  Solder Side w5: v2(93.94,125) 78.94,110 78.94,60 83.94,55 145,55 160.49,70.49 262.68,70.49 288.18,45 333.94,45 358.94,20 358.94,-40 393.94,-75 v2(503.94,-75)
ERASE: Q3.1 R20.2 T6.1 U1.42 | length 594.4
  Component Side w5: Q3.1@41.32,35.59 43.94,38.21 43.94,88.94 T6.1@50,95 ; Q3.1@51.54,35.59 23.94,7.99 23.94,-110.24 R20.2@48.94,-135.24 57.41,-135.24 84.99,-162.82 141.75,-162.82 178.94,-200 248.94,-200 251.4,-197.54 288.94,-197.54 313.94,-172.54 U1.42@313.94,-137
  other v4: 45,95
EXTON: R17.2 U2.21 U6.2 | length 663.3
  Component Side w5: U2.21@803.11,4.37 805.24,6.5 850.83,6.5 864.5,20.17 864.5,66.83 860.5,70.83 v2(860.5,125.9)
  Solder Side w5: U6.2@586.57,327.18 U6.2@586.57,326.65 598.23,315 602.5,315 602.5,306.57 612.57,296.5 621.83,296.5 622.24,296.09 686.59,296.09 692,301.5 790.2,301.5 R17.2@793.94,305.24 854.76,305.24 880,280 880,270 874,264 874,260.67 861.44,248.11 861.44,126.84 v2(860.5,125.9)
GND: C1.1 C3.2 C6.1 C7.1 C9.2 C10.2 C13.2 C14.2 C15.2 C16.2 C17.2 C18.2 C19.2 C20.2 C21.2 C22.2 C23.2 C24.2 C25.2 C26.2 C27.2 C28.2 C29.2 C30.2 C31.2 C32.2 C33.2 C34.2 C35.2 C36.2 C37.2 C38.2 C39.2 C40.2 C41.2 C42.2 C43.2 C44.2 C45.2 C46.2 C47.2 C48.2 C49.2 C51.2 C52.2 C53.2 C54.2 C55.2 C56.2 C57.2 C58.2 C59.2 J1.4 J1.5 J1.6 J2.2 J2.3 J2.4 J2.5 Q3.2 Q5.2 R10.1 R15.1 R17.1 R20.1 R23.1 U1.2 U1.30 U1.34 U1.49 U2.22 U2.32 U2.43 U2.46 U2.49 U3.11 U3.18 U3.20 U4.3 U4.5 U4.8 U4.9 U5.4 U6.4 U7.2 U7.5 X1.2 X2.2 X2.4 Z1.2 Z1.5 | length 2816.8
  Component Side w5: U2.22@803.11,20.12 841.12,20.12 v1(844,23)
  Component Side w7: J1.6@112.2,-230.32 J1.6@112.2,-228.03 ; v2(525,-35) 525,-36.06 530.94,-42 ; U2.32@665.32,79.17 v1(665.32,111.38) ; v1(829.76,335.24) 830,335 C18.2@854.76,335 ; C10.2@908.7,-130 v2@933.46,-130
  Component Side w8: v2(160,-85) 170,-75 U1.34@191.94,-75 ; v1(163.94,5) U1.30@191.94,5 ; C16.2@443.94,-214.76 447.17,-218 478,-218 v2(485,-225) ; U1.2@455.94,-95 v2(488.94,-95) ; 530.94,-42 533.82,-42 534.82,-41 549.73,-41 550.73,-42 568.89,-42 U2.43@569.76,-42.87 ; v1(725,-345) 725,-329.76
  Component Side w10: 40,-195 48.94,-186.06 R20.1@48.94,-164.76 ; v1(40.44,-40) 40.44,-26.69 Q3.2@51.54,-15.59 ; C54.2@178.94,-324.76 225.98,-324.76 X2.4@233.35,-317.4 ; v1(205.94,-282.23) 227.97,-304.27 X2.4@227.97,-312.03 ; X2.2@284.53,-242.6 289.53,-247.6 v1(314.21,-247.6) ; C24.2@400,-285.24 400.24,-285 v1(430,-285) ; C35.2@520,-125.24 520,-110 v5(535,-95) 539.13,-90.87 551.57,-90.87 552.32,-90.12 U2.46@574.76,-90.12 ; X1.2@566.81,-279.41 593.03,-253.19 603.19,-253.19 v1(605,-255) ; v1(585,-175) 585,-170.01 587,-168.01 C6.1@587,-200.24 ; v1(670,270) 671.38,268.62 U3.20@692.91,268.62 ; U3.18@710.63,302.09 710.63,320.63 v2(720,330) ; U3.11@807.09,268.62 833.62,268.62 v1(835,270) ; C3.2@833.94,-239.76 833.94,-263.94 v1(835,-265) ; C1.1@853.94,-294.76 v1(853.94,-275) ; v2(903.94,-335) C9.2@903.94,-305 ; C17.2@904.76,240 905,240.24 v1(905,270) ; v1@1103.94,36.06 Z1.2@1103.94,-32.01 v2(1103.94,-68) Z1.5@1103.94,-102.87 1103.94,-172.43 ccw(c1107.57,-172.43) 1105,-175
  Component Side w15: C55.2@333.94,-334.76 354.17,-334.76 v2(368.94,-320) ; C7.1@700,-329.76 725,-329.76 ; C43.2@923.46,-10 v1(943.94,-10) ; C45.2@923.46,30 v1(943.94,30) ; C13.2@923.46,70 v1(943.94,70) ; C15.2@924.76,110 v1(945,110)
  Solder Side w5: U4.3@402.52,-318.62 408.05,-313.09 420,-313.09 430,-303.09 v1(430,-285) 470.35,-285 480.35,-295 U4.8@480.35,-271.38
  Solder Side w7: v2(525,-35) 529.76,-30.24 C36.2@568.94,-30.24 ; C39.2@563.94,49.76 v2(563.94,75) ; v1(585,-175) 585,-162.81 599.29,-148.52 C31.2@599.29,-121.61 ; v2@933.46,-130 v2(933.94,-130)
  Solder Side w8: v2(295,93.94) 293.94,95 328.7,95 C49.2@333.94,100.24 ; v2(403.94,-15) C40.2@429.17,-15 ; v2(403.94,25) C33.2@429.17,25
  Solder Side w10: v1(183.94,-180) J1.4@183.94,-155 ; J1.4@214.57,-137.8 J1.4@236.14,-137.8 ; J1.4@243.94,-155 v1(243.94,-180) 259.17,-180 C23.2@259.17,-210 ; v1(283.5,181.5) R23.1@305.67,181.5 ; C21.2@343.94,-275 v1(373.94,-275) ; v2(350,85) 370.24,85 375.24,90 C53.2@380,85.24 ; v2(368.94,-320) v2@370.32,-318.62 ; v1(381.14,-250) U4.5@402.52,-271.38 ; C22.2@398.94,-110.24 409.17,-100 v2(425,-100) 439.17,-114.17 C37.2@439.17,-155 ; C26.2@429.76,290 490,290 v2@495,285 ; U7.5@520,-205 U7.2@531.22,-216.22 ; 520,-115.24 520,-110 v5(535,-95) ; 536.73,-217.3 549.2,-217.3 C34.2@549.2,-259.67 ; 549.76,-290 C34.2@549.76,-260.24 ; 570.47,-255 v1(605,-255) ; C25.2@635,-205 635,-215 660,-240 669.76,-230.24 693.31,-230.24 v1(713.33,-210.21) ; C47.2@718.94,50.24 C47.2@723.94,55.24 ; v2(765,335) 793.7,335 R17.1@793.94,334.76 ; C44.2@808.94,20.24 813.7,25 822.2,16.5 828.7,23 v1(844,23)
  Solder Side w15: v2(623.94,-100) 634.17,-110.24 643.94,-110.24 R15.1@643.94,-130.24 ; R10.1@640,-305.24 685.24,-305.24 v1(725,-345) ; C56.2@663.94,140 665.32,138.62 v1(665.32,111.38) ; C30.2@683.94,-130.24 683.94,-100 ; v2(718.94,-100) 718.94,-125.24 C29.2@723.94,-130.24 ; v2(758.94,-100) 758.94,-125.24 C28.2@763.94,-130.24 ; C58.2@920,308.94 v1(920,340) ; C14.2@923.94,-10 v1@938.94,-10 ; C51.2@923.94,30 v1@938.94,30
  Solder Side w30: J1.5@112.2,230.32 158.94,277.05 C32.2@158.94,325
  other v1: 1013.94,-300 1153.94,-300 1203.94,-300 1253.94,-300 1300,-300 1350,-300 1003.94,-250 1053.94,-250 1103.94,-250 1153.94,-250 1203.94,-250 1253.94,-250 1300,-250 1350,-250 978.94,-235 978.94,-215 1003.94,-200 1053.94,-200 1103.94,-200 1153.94,-200 203.94,-180 223.94,-180 953.94,-175 995,-175 1040,-175 1080,-175 1130,-175 1180,-165 1150,-150 1103.94,-135 1225,-110 1275,-110 1320,-110 1370,-110 1170,-105 1200,-95 1225,-75 1275,-75 1320,-75 1370,-75 1103.94,2.03 980,35 1010,40 1053.94,40 1100,40 846,45 1140,50 968.94,65 1205,70 1255,70 1300,70 1350,70 1003.94,80 1053.94,80 1100,80 1150,80 1205,110 1255,110 1301.06,110 1351.06,110 968.94,115 1003.94,150 1053.94,150 1103.94,150 1153.94,150 953.94,180 973.94,180 1003.94,200 1053.94,200 1103.94,200 1153.94,200 1003.94,250 1053.94,250 1103.94,250 1153.94,250 1203.94,250 1253.94,250 1300,250 1350,250 243.94,255 275,255 950,270 243.94,275 160,290 35,295 243.94,295 1003.94,300 1053.94,300 1103.94,300 1153.94,300 1203.94,300 1253.94,300 1300,300 1350,300 50,330 626,349 655,349
  other v2: 840,-335 865,-335 843.94,-155 333.94,-105 668.94,-100 223.94,-90 258.94,-90 623.94,-35 668.94,-35 718.94,-35 758.94,-35 623.94,30 668.94,30 725,30 755,30 501,261.54 446.5,276.5 501,288.35
GREEN-LED: R11.1 U1.9 | length 741.6
  Component Side w5: v2(105.15,146.32) 100.74,146.32 44.7,202.36 44.7,274.7 100,330 R11.1@124.17,330 ; U1.9@455.94,45 483.94,45 v2(491.44,45)
  Solder Side w5: v2(105.15,146.32) 105.33,146.5 130.77,146.5 153.94,123.33 153.94,110.68 174.13,90.49 270.97,90.49 296.46,65 343.08,65 361.54,46.54 497.4,46.54 495.86,45 v2(491.44,45)
LPS25-INT: U1.23 U4.7 | length 1442.7
  Component Side w5: U1.23@233.94,127 233.94,143.94 250,160 v1(250,185) ; v1(470,-246.26) 470,-340 v1(475,-345)
  Solder Side w5: v1(250,185) 256.08,178.92 256.08,169.88 261.44,164.52 261.44,111.07 250.86,100.49 178.27,100.49 163.94,114.83 163.94,127.48 128.6,162.82 97.82,162.82 65,130 65,67.56 45,47.56 45,-15 58.94,-28.94 58.94,-150 23.94,-185 23.94,-265.79 38.94,-280.79 38.94,-300 62.44,-323.5 78.5,-323.5 105,-350 473.28,-350 475,-348.28 v1(475,-345) ; U4.7@450.75,-258.58 464.33,-245 465.59,-246.26 v1(470,-246.26)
